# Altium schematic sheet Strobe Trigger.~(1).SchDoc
size B; Organization: Monterey Bay Aquarium Research Institute; Address1: 7700 Sandholdt Rd; Address2: Moss Landing, CA 95039-9644; CompanyName: MBARI
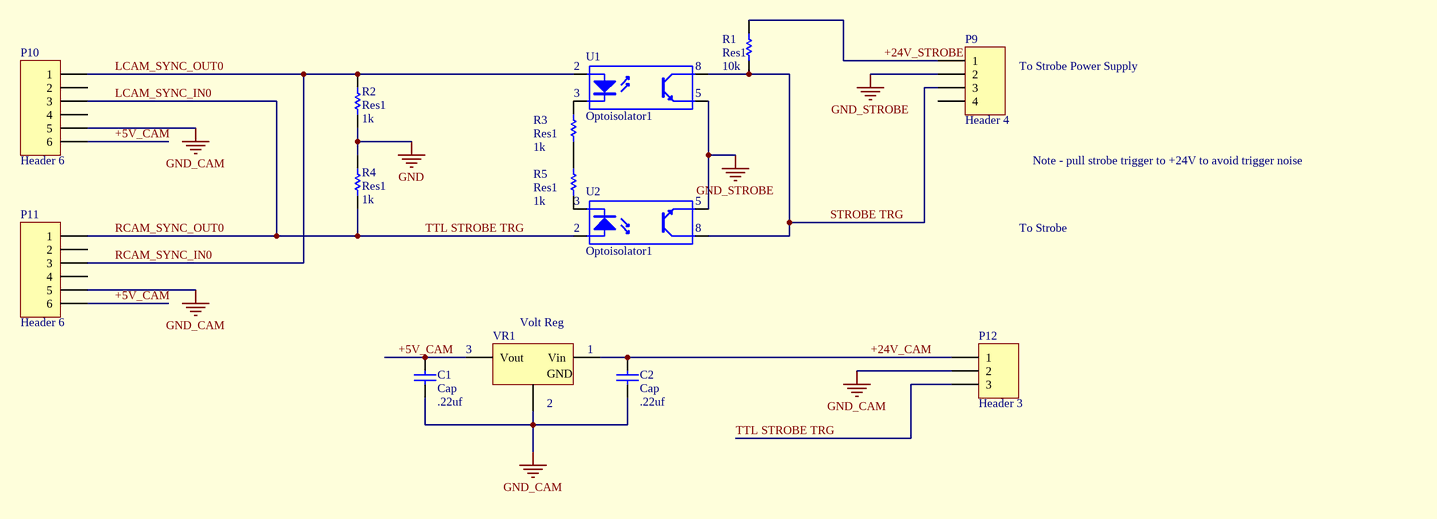
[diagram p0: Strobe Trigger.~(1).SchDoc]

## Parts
C1  Cap  value .22uf  [RAD-0.3]
C2  Cap  value .22uf  [RAD-0.3]
P9  Header 4  [HDR1X4]
P10  Header 6  [HDR1X6]
P11  Header 6  [HDR1X6]
P12  Header 3  [HDR1X3]
R1  Res1  value 10k  [AXIAL-0.3]
R2  Res1  value 1k  [AXIAL-0.3]
R3  Res1  value 1k  [AXIAL-0.3]
R4  Res1  value 1k  [AXIAL-0.3]
R5  Res1  value 1k  [AXIAL-0.3]
U1  Optoisolator1  [DIP-4]
U2  Optoisolator1  [DIP-4]
VR1  Volt Reg  [D2PAK_N]

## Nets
GND: R2.1 R4.2
GND_CAM: C1.1 C2.1 P10.5 P11.5 P12.2 VR1.2(GND)
GND_STROBE: P9.2 U1.3(E) U2.3(E)
+5V_CAM: C1.2 P10.6 P11.6 VR1.3(Vout)
+24V_CAM: C2.2 P12.1 VR1.1(Vin)
+24V_STROBE: P9.1 R1.2
LCAM_SYNC_IN0: P10.3 P11.1 P12.3 R4.1 U2.1(A)  [also labelled RCAM_SYNC_OUT0, TTL STROBE TRG]
LCAM_SYNC_OUT0: P10.1 P11.3 R2.2 U1.1(A)  [also labelled RCAM_SYNC_IN0]
STROBE TRG: P9.3 R1.1 U1.4(C) U2.4(C)
NetR3_1: R3.1 R5.2
NetR3_2: R3.2 U1.2(K)
NetR5_1: R5.1 U2.2(K)

Not connected (* = marked no-connect by the designer): P9 4; P10 2 4; P11 2 4

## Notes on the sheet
- (near U1) 2
- 3
- (near U1) 8
- (near U1) 5
- To Strobe Power Supply
- Note - pull strobe trigger to +24V to avoid trigger noise
- (near U2) 2
- (near R5) 3
- (near U2) 8
- (near U2) 5
- To Strobe
- (near VR1) 3
- (near VR1) 1
- (near VR1) 2

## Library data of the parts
C1 C2 = Cap: Capacitor
P9 = Header 4: Header, 4-Pin
P10 P11 = Header 6: Header, 6-Pin
P12 = Header 3: Header, 3-Pin
R1-R5 = Res1: Resistor
U1 U2 = Optoisolator1: 4-Pin Phototransistor Optocoupler
VR1 = Volt Reg: Voltage Regulator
